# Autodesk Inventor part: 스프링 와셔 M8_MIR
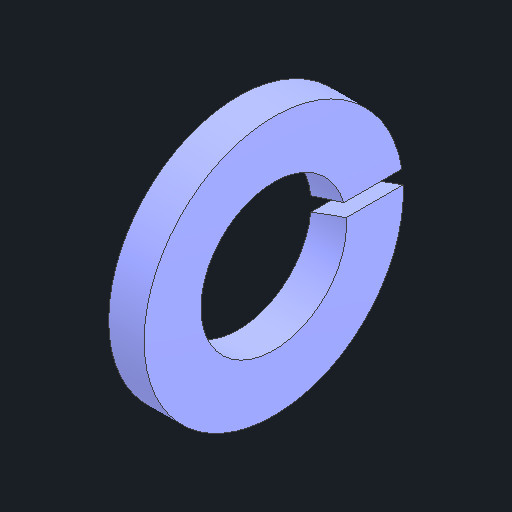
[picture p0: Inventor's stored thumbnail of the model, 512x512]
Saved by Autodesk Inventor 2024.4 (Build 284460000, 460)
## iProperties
Created: 2025-10
Part Number: 스프링 와셔 M8_MIR
Material: 강철, 연강
Description: 스프링 잠금 와셔
Document SubType Name: Modeling
Designer: user
Density: 7.85 g/cm^3
Appearance: 기본값
Author: jhkim
Sending System: Autodesk Inventor 2026
Preprocessor: ST-DEVELOPER v20.1
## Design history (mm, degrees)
derived "스프링 와셔 M8.ipt"
feature "솔리드1::스프링 와셔 M8.ipt" dims "d0" = 10
tag "피쳐 태그1"
node "솔리드1"
